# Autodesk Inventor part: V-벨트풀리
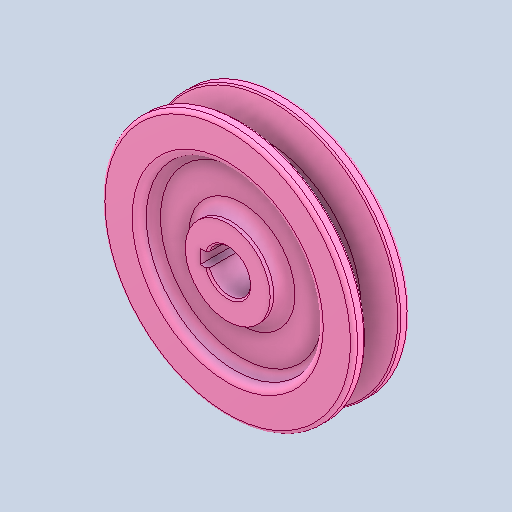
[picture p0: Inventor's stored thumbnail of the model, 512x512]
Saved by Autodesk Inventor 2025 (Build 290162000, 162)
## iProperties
Created: 2024-08
Part Number: V-벨트풀리
Material: 강철, 연강
Document SubType Name: Modeling
Designer: hsj03
Density: 7.86 g/cm^3
Appearance: 기본값
Author: jhkim
Sending System: Autodesk Inventor 2025
Preprocessor: ST-DEVELOPER v20
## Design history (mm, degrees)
feature "Solid1"
node "솔리드1"
